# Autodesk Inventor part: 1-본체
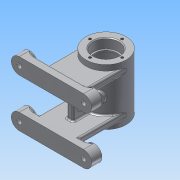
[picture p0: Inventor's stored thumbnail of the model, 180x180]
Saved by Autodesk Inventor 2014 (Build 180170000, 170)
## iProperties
Created: 2007-09
Part Number: 1-본체
Material: 알루미늄 6061
Document SubType Name: Modeling
Designer: 103-28
Density: 2.71 g/cm^3
Appearance: 알루미늄 - 평지
Mass: 357.757 g
Surface Area: 471.053 cm^2
Volume: 132.014 cm^3
Author: 103-28
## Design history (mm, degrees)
sketch "스케치1"
  geometry: C1 r 25 at (0, 0); 1 further point
  constraints: 1 centre point, 1 coincident
  dimensions: "d0" = 50 diameter of C1
extrude "돌출1" new body sketch "스케치1" stored distance "d1" = 70; taper "d2" = 0 deg
node "작업 평면1"
sketch "스케치2"
  geometry: C1 r 10 at (-40, 30); C2 r 10 at (40, 30); C3 r 10 at (-40, -30); C4 r 10 at (40, -30); 1 further point
  constraints: 4 centre point, 3 equal radius, 2 horizontal alignment, 2 vertical alignment
  dimensions: "d4" = 20 diameter of C1; "d5" = 80 distance of C2.centre C1.centre; "d7" = 40 horizontal distance of point (0, 0) C1.centre; "d14" = 80 dimension on C3 C1; "d15" = 30 vertical distance of point (0, 0) C1.centre
extrude "돌출2" join sketch "스케치2" distance "d9" = 13; taper "d10" = 0 deg
sketch "스케치5"
  geometry: L1 (-80, 10)-(0, 10); L2 (-80, -10)-(0, -10); L3 (-80, -50)-(0, -50); L4 (-80, -70)-(0, -70); A1 r 10 centre (0, 0) between (0, 10) and (0, -10) reference; A2 r 10 centre (0, -60) between (0, -50) and (0, -70) reference; A3 r 10 centre (-80, -60) between (-80, -50) and (-80, -70) reference; A4 r 10 centre (-80, 0) between (-80, 10) and (-80, -10) reference; 1 further point
  constraints: 8 end point, 8 point on circle, 7 tangent, 1 parallel
extrude "돌출4" join sketch "스케치5" distance "d16" = 10; taper "d17" = 0 deg
sketch "스케치6"
  geometry: L1 (0, 10)-(80, 10) reference; L2 (0, 0)-(0, 10) reference; L3 (15, 10)-(15, 68); L4 (65, 10)-(65, 68); A1 r 25 centre (40, 68) between (15, 68) and (65, 68) reference; 1 further point
  constraints: 4 end point, 2 parallel, 2 perpendicular, 2 point on circle, 2 point on line, 1 tangent
extrude "돌출5" join sketch "스케치6" distance "d18" = 8; taper "d19" = 0 deg
sketch "스케치7"
  geometry: L1 (0, 10)-(80, 10) reference; L2 (15, 10)-(15, 68); L3 (65, 10)-(65, 68); A1 r 25 centre (40, 68) between (15, 68) and (65, 68) reference; 1 further point
  constraints: 4 end point, 2 point on circle, 2 point on line, 2 tangent, 1 parallel, 1 perpendicular
extrude "돌출6" join sketch "스케치7" distance "d20" = 8; taper "d21" = 0 deg
node "작업 평면3"
sketch "스케치8"
  geometry: L1 (-45, 20)-(-45, -20); L2 (-45, 20)-(-14.132, 20); L3 (-14.132, 20)-(-14.132, -20); L4 (-14.132, -20)-(-45, -20); L5 (-25, -35)-(-25, 35) reference; L6 (25, 35)-(-25, 35) reference; 1 further point
  constraints: 8 end point, 2 perpendicular, 1 parallel
  dimensions: "d136" = 20 distance between parallel lines of L1 L5; "d137" = 30.86823 distance between parallel lines of L1 L3; "d138" = 40 distance between parallel lines of L4 L2; "d139" = 15 distance between parallel lines of L6 L2
extrude "돌출7" join sketch "스케치8" stored distance "d24" = 8; taper "d25" = 0 deg
node "작업 평면5"
  node "작업 평면4"
sketch "스케치9"
  geometry: C1 r 5 at (0, 0); 1 further point
  constraints: 1 centre point, 1 coincident
  dimensions: "d27" = 10 diameter of C1
extrude "돌출8" join sketch "스케치9" stored distance "d28" = 8; taper "d29" = 0 deg
sketch "스케치10"
  geometry: L1 (20, -24.678)-(20, -45) reference; L2 (-8, -31.5)-(8, -31.5); L3 (8, -38.5)-(-8, -38.5); L4 (-5, 28)-(5, 28) reference; L5 (20, -68)-(40, -68) reference; A1 r 3.5 centre (8, -35) between (8, -38.5) and (8, -31.5); A2 r 3.5 centre (-8, -35) between (-8, -31.5) and (-8, -38.5); 4 further points
  constraints: 4 end point, 4 point on circle, 3 tangent, 2 centre point, 2 midpoint, 1 equal radius, 1 parallel, 1 perpendicular, 1 vertical alignment
  dimensions: "d30" = 3.5 radius of A1; "d31" = 23 dimension on A1 A2; "d32" = 33 distance from line of L5 A1.centre
extrude "돌출9" cut sketch "스케치10" stored distance "d33" = 0; taper "d34" = 0 deg
hole "구멍1" diameter "d37" = 28; stored, may be unused: countersink angle "d41" = 90 deg, drill point angle "d43" = 0 deg; dims "d35" = 10, "d36" = 10, "d38" = 6, "d39" = 32, "d40" = 12, "d42" = 14
hole "구멍2" diameter "d46" = 42; stored, may be unused: countersink angle "d50" = 90 deg, drill point angle "d52" = 0 deg; dims "d44" = 10, "d45" = 10, "d47" = 6, "d48" = 32, "d49" = 12, "d51" = 42
sketch "스케치11"
  geometry: C1 r 16 at (0, 0) reference; 1 further point
  constraints: 1 vertical alignment
  dimensions: "d53" = 20 distance of C1.centre point (0, 20)
hole "구멍3" sketch "스케치11" at (0, 20) diameter "d54" = 3.242; stored, may be unused: countersink angle "d58" = 90 deg, drill point angle "d60" = 118 deg; dims "d55" = 8, "d56" = 32, "d57" = 12, "d59" = 10
hole "구멍4" diameter "d66" = 5.188; stored, may be unused: countersink angle "d70" = 90 deg, drill point angle "d72" = 118 deg; dims "d64" = 10, "d65" = 10, "d67" = 8, "d68" = 32, "d69" = 12, "d71" = 10
node "작업 평면6"
sketch "스케치12"
  geometry: L1 (0, 0)-(14, -24.249); L2 (0, 0)-(0, -25); 1 further point
  constraints: 4 end point, 1 vertical, 1 vertical alignment, 1 other
  dimensions: "d74" = 30 deg angle of L1 L2; "d76" = 28 distance of L1.start L1.end
node "작업 평면7"
sketch "스케치13"
  geometry: C1 r 6 at (0, 0); 2 further points
  constraints: 1 centre point, 1 coincident
  dimensions: "d77" = 12 diameter of C1
extrude "돌출10" join sketch "스케치13" stored distance "d78" = 0; taper "d79" = 0 deg
hole "구멍5" diameter "d82" = 5.188; stored, may be unused: countersink angle "d86" = 90 deg, drill point angle "d88" = 118 deg; dims "d80" = 10, "d81" = 10, "d83" = 8, "d84" = 32, "d85" = 12, "d87" = 10
hole "구멍6" diameter "d91" = 6; stored, may be unused: countersink angle "d95" = 90 deg, drill point angle "d97" = 118 deg; dims "d89" = 10, "d90" = 10, "d92" = 8, "d93" = 12, "d94" = 4, "d96" = 10
hole "구멍7" diameter "d100" = 6; stored, may be unused: countersink angle "d104" = 90 deg, drill point angle "d106" = 118 deg; dims "d98" = 10, "d99" = 10, "d101" = 8, "d102" = 12, "d103" = 4, "d105" = 10
hole "구멍8" diameter "d109" = 6; stored, may be unused: countersink angle "d113" = 90 deg, drill point angle "d115" = 118 deg; dims "d107" = 10, "d108" = 10, "d110" = 8, "d111" = 12, "d112" = 4, "d114" = 10
hole "구멍9" diameter "d118" = 6; stored, may be unused: countersink angle "d122" = 90 deg, drill point angle "d124" = 118 deg; dims "d116" = 10, "d117" = 10, "d119" = 8, "d120" = 12, "d121" = 4, "d123" = 10
chamfer "모따기1" distance "d125" = 1; stored, may be unused: second distance "d126" = 2, angle "d127" = 45 deg
fillet "모깎기1" dims "d128" = 0.3, "d129" = 2, "d141" = 3
fillet "모깎기2" dims "d130" = 2
fillet "모깎기3" dims "d131" = 2
node "작업 평면8"
sketch "스케치14"
  geometry: L1 (-25, -35)-(-25, 35) reference; L2 (-25, -35)-(25, -35) reference; 2 further points
  constraints: 1 other
  dimensions: "d132" = 25 distance from line of L1 point (0, 0); "d133" = 35 distance from line of L2 point (0, 0)
feature "엠보싱1" sketch "스케치14" dims "d134" = 0.5, "d135" = 0
fillet "모깎기4" dims "d140" = 2
fillet "모깎기5" dims "d142" = 0.3
chamfer "모따기2" distance "d143" = 1; stored, may be unused: second distance "d144" = 2, angle "d145" = 45 deg
node "솔리드1"
pattern_circular "원형 패턴1" dims angle "d62" = 360 deg
mirror "대칭1"
node "투영된 루프5"
node "투영된 루프6"
node "투영된 루프7"
node "투영된 루프8"
node "투영된 루프9"
other parameters: "d3" = -68, "d22" = 0, "d26" = 3, "d73" = 0
